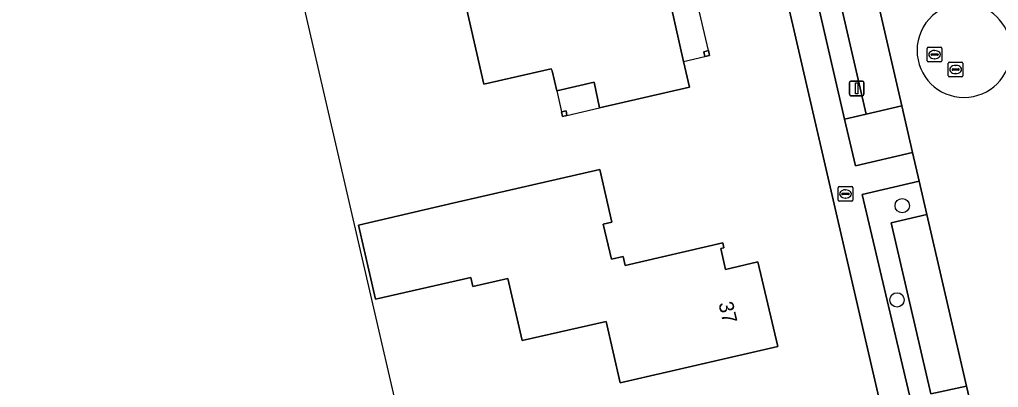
# Model space of a CAD drawing. Extents: x 156412 to 157779, y 382335 to 383768.
# Drawn here: x 156633.8 to 156700.6, y 382775.4 to 382800.5 of the extents above; entities that cross this region are included whole.
import ezdxf

# ---------------------------------------------------------------- set-up
doc = ezdxf.new("R2010")
doc.units = 0
for name, color, linetype in [('IMGEO_Berm_groen', 7, 'Continuous'), ('IMGEO_Boom', 7, 'Continuous'), ('IMGEO_Brandkraan', 7, 'Continuous'), ('IMGEO_Erf', 7, 'Continuous'), ('IMGEO_Lichtmast', 7, 'Continuous'), ('IMGEO_Pand', 7, 'Continuous'), ('IMGEO_Pand_nummerreeks', 7, 'Continuous'), ('IMGEO_Pand_overbouw', 7, 'Continuous'), ('IMGEO_Parkeervlak_halfverhard', 7, 'Continuous'), ('IMGEO_Rijbaan_lokaal_gesloten', 7, 'Continuous'), ('IMGEO_Rijbaan_lokaal_open', 7, 'Continuous'), ('IMGEO_Rioolput', 7, 'Continuous'), ('IMGEO_Voetpad_open', 7, 'Continuous')]:
    doc.layers.add(name, color=color, linetype=linetype)

msp = doc.modelspace()

# ---------------------------------------------------------------- linework, layer by layer
at = {"layer": 'IMGEO_Berm_groen'}
for points in [[(156689.485, 382803.272), (156688.01, 382802.932), (156690.119, 382793.734), (156691.599, 382794.08)], [(156695.215, 382789.506), (156692.782, 382788.931), (156691.321, 382788.585), (156695.122, 382772.473), (156696.517, 382772.802), (156698.95, 382773.376), (156698.458, 382775.501), (156696.018, 382774.957), (156693.309, 382786.654), (156695.744, 382787.222)]]:
    msp.add_lwpolyline(points, close=True, dxfattribs=at)
at = {"layer": 'IMGEO_Boom'}
for centre in [(156694.065, 382787.818), (156693.707, 382781.385)]:
    msp.add_circle(centre, 0.489, dxfattribs=at)
at = {"layer": 'IMGEO_Brandkraan'}
for p, q in [((156689.762, 382789.122), (156690.614, 382789.122)), ((156689.687, 382788.196), (156689.687, 382789.048)), ((156689.946, 382788.616), (156689.946, 382788.628)), ((156690.384, 382788.579), (156689.986, 382788.579)), ((156689.989, 382788.665), (156690.387, 382788.665)), ((156690.175, 382788.902), (156690.2, 382788.902)), ((156690.43, 382788.628), (156690.43, 382788.616)), ((156690.688, 382789.048), (156690.688, 382788.196)), ((156690.614, 382788.122), (156689.762, 382788.122)), ((156690.198, 382788.342), (156690.173, 382788.342))]:
    msp.add_line(p, q, dxfattribs=at)
for points in [[(156689.762, 382789.122), (156690.614, 382789.122)], [(156689.687, 382788.196), (156689.687, 382789.048)], [(156690.688, 382789.048), (156690.688, 382788.196)], [(156690.614, 382788.122), (156689.762, 382788.122)]]:
    msp.add_lwpolyline(points, dxfattribs=at)
for centre, radius, start, end in [((156689.764, 382789.046), 0.0765, 91.55205, 178.44795), ((156689.764, 382789.046), 0.0765, 91.55205, 178.44795), ((156690.612, 382789.046), 0.0765, 1.55205, 88.44795), ((156690.612, 382789.046), 0.0765, 1.55205, 88.44795), ((156689.986, 382788.625), 0.0403, 85.87752, 175.75265), ((156689.983, 382788.615), 0.0366, 178.93798, 274.71019), ((156690.387, 382788.622), 0.043, 264.86636, 352.45326), ((156690.391, 382788.627), 0.0386, 1.73085, 96.63898), ((156689.764, 382788.198), 0.0765, 181.55205, 268.44795), ((156689.764, 382788.198), 0.0765, 181.55205, 268.44795), ((156690.612, 382788.198), 0.0765, 271.55205, 358.44795), ((156690.612, 382788.198), 0.0765, 271.55205, 358.44795)]:
    msp.add_arc(centre, radius, start, end, dxfattribs=at)
for centre, major_axis, ratio, start_param, end_param in [((156690.174, 382788.622), (-0.387, 0.002), 0.722429, 4.712389, 7.853982), ((156690.199, 382788.622), (-0.39, 0.002), 0.717154, 1.570796, 4.712389)]:
    msp.add_ellipse(centre, major_axis=major_axis, ratio=ratio, start_param=start_param, end_param=end_param, dxfattribs=at)
at = {"layer": 'IMGEO_Erf'}
for points in [[(156662.663, 382894.621), (156655.658, 382892.624), (156652.152, 382891.665), (156646.148, 382889.742), (156640.021, 382887.678), (156636.864, 382886.529), (156633.896, 382885.409), (156633.769, 382885.37), (156667.046, 382741.442)], [(156694.882, 382764.275), (156665.21, 382892.732)]]:
    msp.add_lwpolyline(points, dxfattribs=at)
for points in [[(156675.778, 382808.226), (156676.601, 382804.483), (156679.273, 382805.109), (156680.034, 382801.82), (156678.286, 382801.416), (156679.128, 382797.673), (156679.524, 382795.913), (156673.388, 382794.503), (156673.009, 382796.255), (156670.471, 382795.673), (156670.155, 382797.037), (156670.089, 382797.168), (156665.481, 382796.126), (156663.974, 382802.73), (156665.447, 382803.066), (156665.416, 382803.203), (156668.926, 382804.004), (156669.22, 382802.718), (156670.506, 382803.011), (156669.636, 382806.823)], [(156680.821, 382798.411), (156680.897, 382798.078), (156680.584, 382798.006), (156680.507, 382798.339)], [(156671.163, 382793.99), (156670.856, 382793.918), (156670.786, 382794.224), (156671.099, 382794.294)], [(156663.457, 382788.005), (156673.404, 382790.298), (156674.235, 382786.693), (156673.641, 382786.556), (156674.193, 382784.158), (156675, 382784.341), (156675.136, 382783.739), (156681.807, 382785.279), (156681.881, 382784.951), (156681.676, 382784.905), (156681.998, 382783.468), (156684.201, 382783.976), (156685.564, 382778.209), (156674.807, 382775.722), (156673.837, 382779.918), (156668.108, 382778.608), (156667.121, 382782.845), (156664.732, 382782.299), (156664.592, 382782.912), (156658.084, 382781.424), (156656.923, 382786.499)]]:
    msp.add_lwpolyline(points, close=True, dxfattribs=at)
at = {"layer": 'IMGEO_Lichtmast'}
for p, q in [((156690.454, 382795.43), (156690.454, 382796.23)), ((156690.454, 382796.23), (156690.454, 382795.43)), ((156690.554, 382796.33), (156691.344, 382796.33)), ((156691.344, 382796.33), (156690.554, 382796.33)), ((156691.444, 382796.23), (156691.444, 382795.43)), ((156691.444, 382795.43), (156691.444, 382796.23)), ((156691.344, 382795.33), (156690.554, 382795.33)), ((156690.554, 382795.33), (156691.344, 382795.33))]:
    msp.add_line(p, q, dxfattribs=at)
msp.add_lwpolyline([(156690.874, 382796.205), (156691.024, 382796.205), (156691.024, 382795.455), (156690.874, 382795.455), (156690.874, 382796.205)], dxfattribs=at)
for centre, start, end in [((156690.554, 382796.23), 90, 180), ((156690.554, 382796.23), 90, 180), ((156691.344, 382796.23), 0, 90), ((156691.344, 382796.23), 360, 90), ((156690.554, 382795.43), 180, 270), ((156690.554, 382795.43), 180, 270), ((156691.344, 382795.43), 270, 0), ((156691.344, 382795.43), 270, 0)]:
    msp.add_arc(centre, 0.1, start, end, dxfattribs=at)
at = {"layer": 'IMGEO_Pand'}
for points in [[(156673.388, 382794.503), (156679.524, 382795.913), (156679.128, 382797.673), (156678.286, 382801.416), (156680.034, 382801.82), (156679.273, 382805.109), (156676.601, 382804.483), (156675.778, 382808.226), (156669.636, 382806.823), (156670.506, 382803.011), (156669.22, 382802.718), (156668.926, 382804.004), (156665.416, 382803.203), (156665.447, 382803.066), (156663.974, 382802.73), (156665.481, 382796.126), (156670.089, 382797.168), (156670.155, 382797.037), (156670.471, 382795.673), (156673.009, 382796.255)], [(156680.821, 382798.411), (156680.507, 382798.339), (156680.584, 382798.006), (156680.897, 382798.078)], [(156671.163, 382793.99), (156671.099, 382794.294), (156670.786, 382794.224), (156670.856, 382793.918)], [(156681.676, 382784.905), (156681.881, 382784.951), (156681.807, 382785.279), (156675.136, 382783.739), (156675, 382784.341), (156674.193, 382784.158), (156673.641, 382786.556), (156674.235, 382786.693), (156673.404, 382790.298), (156663.457, 382788.005), (156656.923, 382786.499), (156658.084, 382781.424), (156664.592, 382782.912), (156664.732, 382782.299), (156667.121, 382782.845), (156668.108, 382778.608), (156673.837, 382779.918), (156674.807, 382775.722), (156685.564, 382778.209), (156684.201, 382783.976), (156681.998, 382783.468)]]:
    msp.add_lwpolyline(points, close=True, dxfattribs=at)
at = {"layer": 'IMGEO_Pand_overbouw'}
for points in [[(156680.821, 382798.411), (156680.034, 382801.82), (156678.286, 382801.416), (156679.128, 382797.673), (156680.584, 382798.006), (156680.507, 382798.339)], [(156671.163, 382793.99), (156673.388, 382794.503), (156673.009, 382796.255), (156670.471, 382795.673), (156670.786, 382794.224), (156671.099, 382794.294)]]:
    msp.add_lwpolyline(points, close=True, dxfattribs=at)
at = {"layer": 'IMGEO_Parkeervlak_halfverhard'}
for points in [[(156691.921, 382803.833), (156689.485, 382803.272), (156691.599, 382794.08), (156694.033, 382794.649)], [(156695.744, 382787.222), (156693.309, 382786.654), (156696.018, 382774.957), (156698.458, 382775.501)]]:
    msp.add_lwpolyline(points, close=True, dxfattribs=at)
at = {"layer": 'IMGEO_Rijbaan_lokaal_gesloten'}
msp.add_lwpolyline([(156691.921, 382803.833), (156694.033, 382794.649), (156694.767, 382791.455), (156695.215, 382789.506), (156695.744, 382787.222), (156698.458, 382775.501), (156698.95, 382773.376), (156699.724, 382770.058), (156701.127, 382763.998)], dxfattribs=at)
for centre, radius, start, end in [((156698.283, 382798.424), 3.207, 83.93348, 180.01595), ((156698.284, 382798.422), 3.209, 0.01331, 81.44456), ((156698.285, 382798.424), 3.209, 180.00893, 359.99107)]:
    msp.add_arc(centre, radius, start, end, dxfattribs=at)
at = {"layer": 'IMGEO_Rijbaan_lokaal_open'}
msp.add_lwpolyline([(156694.033, 382794.649), (156691.599, 382794.08), (156690.119, 382793.734), (156690.864, 382790.532), (156694.767, 382791.455)], close=True, dxfattribs=at)
for centre, radius, start, end in [((156698.283, 382798.424), 3.207, 83.93348, 180.01595), ((156698.284, 382798.422), 3.209, 0.01331, 81.44456), ((156698.285, 382798.424), 3.209, 180.00893, 359.99107)]:
    msp.add_arc(centre, radius, start, end, dxfattribs=at)
at = {"layer": 'IMGEO_Rioolput'}
for p, q in [((156695.771, 382797.714), (156695.771, 382798.566)), ((156695.846, 382798.64), (156696.698, 382798.64)), ((156696.772, 382798.566), (156696.772, 382797.714)), ((156696.03, 382798.134), (156696.03, 382798.146)), ((156696.468, 382798.097), (156696.07, 382798.097)), ((156696.073, 382798.183), (156696.471, 382798.183)), ((156696.282, 382797.86), (156696.257, 382797.86)), ((156696.259, 382798.42), (156696.284, 382798.42)), ((156696.514, 382798.146), (156696.514, 382798.134)), ((156696.698, 382797.64), (156695.846, 382797.64)), ((156697.213, 382796.696), (156697.213, 382797.548)), ((156697.288, 382797.622), (156698.14, 382797.622)), ((156697.472, 382797.116), (156697.472, 382797.128)), ((156697.515, 382797.165), (156697.913, 382797.165)), ((156697.701, 382797.402), (156697.726, 382797.402)), ((156697.956, 382797.128), (156697.956, 382797.116)), ((156698.214, 382797.548), (156698.214, 382796.696)), ((156698.14, 382796.622), (156697.288, 382796.622)), ((156697.91, 382797.079), (156697.512, 382797.079)), ((156697.724, 382796.842), (156697.699, 382796.842))]:
    msp.add_line(p, q, dxfattribs=at)
for points in [[(156695.771, 382797.714), (156695.771, 382798.566)], [(156695.846, 382798.64), (156696.698, 382798.64)], [(156696.772, 382798.566), (156696.772, 382797.714)], [(156696.698, 382797.64), (156695.846, 382797.64)], [(156697.213, 382796.696), (156697.213, 382797.548)], [(156697.288, 382797.622), (156698.14, 382797.622)], [(156698.214, 382797.548), (156698.214, 382796.696)], [(156698.14, 382796.622), (156697.288, 382796.622)]]:
    msp.add_lwpolyline(points, dxfattribs=at)
for centre, radius, start, end in [((156695.848, 382798.564), 0.0765, 91.55205, 178.44795), ((156695.848, 382798.564), 0.0765, 91.55205, 178.44795), ((156696.696, 382798.564), 0.0765, 1.55205, 88.44795), ((156696.696, 382798.564), 0.0765, 1.55205, 88.44795), ((156696.07, 382798.143), 0.0403, 85.87752, 175.75265), ((156696.067, 382798.133), 0.0366, 178.93798, 274.71019), ((156696.471, 382798.14), 0.043, 264.86636, 352.45326), ((156696.475, 382798.145), 0.0386, 1.73085, 96.63898), ((156695.848, 382797.716), 0.0765, 181.55205, 268.44795), ((156695.848, 382797.716), 0.0765, 181.55205, 268.44795), ((156696.696, 382797.716), 0.0765, 271.55205, 358.44795), ((156696.696, 382797.716), 0.0765, 271.55205, 358.44795), ((156697.29, 382797.546), 0.0765, 91.55205, 178.44795), ((156697.29, 382797.546), 0.0765, 91.55205, 178.44795), ((156697.512, 382797.125), 0.0403, 85.87752, 175.75265), ((156697.509, 382797.115), 0.0366, 178.93798, 274.71019), ((156697.913, 382797.122), 0.043, 264.86636, 352.45326), ((156697.917, 382797.127), 0.0386, 1.73085, 96.63898), ((156698.138, 382797.546), 0.0765, 1.55205, 88.44795), ((156698.138, 382797.546), 0.0765, 1.55205, 88.44795), ((156697.29, 382796.698), 0.0765, 181.55205, 268.44795), ((156697.29, 382796.698), 0.0765, 181.55205, 268.44795), ((156698.138, 382796.698), 0.0765, 271.55205, 358.44795), ((156698.138, 382796.698), 0.0765, 271.55205, 358.44795)]:
    msp.add_arc(centre, radius, start, end, dxfattribs=at)
for centre, major_axis, ratio, start_param, end_param in [((156696.258, 382798.14), (-0.387, 0.002), 0.722429, 4.712389, 7.853982), ((156696.283, 382798.14), (-0.39, 0.002), 0.717154, 1.570796, 4.712389), ((156697.7, 382797.122), (-0.387, 0.002), 0.722429, 4.712389, 7.853982), ((156697.725, 382797.122), (-0.39, 0.002), 0.717154, 1.570796, 4.712389)]:
    msp.add_ellipse(centre, major_axis=major_axis, ratio=ratio, start_param=start_param, end_param=end_param, dxfattribs=at)
at = {"layer": 'IMGEO_Voetpad_open'}
for points in [[(156665.21, 382892.732), (156694.882, 382764.275), (156695.147, 382762.767), (156695.949, 382759.629), (156696.399, 382757.676), (156708.634, 382704.563), (156717.566, 382666.506), (156725.025, 382634.25), (156725.115, 382633.86), (156726.112, 382629.552), (156727.385, 382624.03), (156727.839, 382622.057), (156731.446, 382606.382)], [(156701.911, 382742.773), (156700.241, 382750), (156699.805, 382751.887), (156699.031, 382755.211), (156697.809, 382760.618), (156697.255, 382763.084), (156695.881, 382769.156), (156695.122, 382772.473), (156691.321, 382788.585), (156692.782, 382788.931), (156695.215, 382789.506), (156694.767, 382791.455), (156690.864, 382790.532), (156690.119, 382793.734), (156688.01, 382802.932)]]:
    msp.add_lwpolyline(points, dxfattribs=at)

# ---------------------------------------------------------------- texts
at = {"layer": 'IMGEO_Pand_nummerreeks'}
msp.add_text('37', height=1, rotation=283.29814, dxfattribs=at).set_placement((156681.501, 382781.142))

doc.saveas('drawing.dxf')
